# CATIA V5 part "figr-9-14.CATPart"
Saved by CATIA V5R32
Part number: Part2
Bounding box of the stored display mesh (mm): x -33.329 to 47.777, y -126.495 to 121.369, z -47.545 to 64.906
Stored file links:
  D:\PROJECTS\Project 2022\CATIA V5 6R 2022\Resources\Part Files\c09_catia_v5_6r2022_prt\c09_catia_v5_6r2022_prt\figr-9-14.CATPart
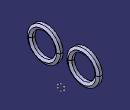
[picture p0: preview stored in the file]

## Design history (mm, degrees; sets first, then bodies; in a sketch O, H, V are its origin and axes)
Body1 (main body)
  Sketch1 on yz-plane, origin (0, 0, 0), H (0, 1, 0), V (0, 0, 1)
    circle A1 centre (-70.2613, 8.6726) radius 37.6716
    circle A2 centre (65.3061, 8.6726) radius 37.5
    radius A2 = 37.5
    radius A1 = 37.6716
  Plane1: type Angle, RefPlane yz-plane, Direction Sketch1.V, Angle 10
  Plane2: type Offset, RefPlane Plane1, Offset 55
  Sketch2 on Plane2, origin (44.5537, 64.0556, 0), H (-0.1736, 0.9848, 0), V (0, 0, 1)
    point P1 (-10.3597, -23.8575)
    point P2 (-2.157, -28.5933)
    point P3 (-2.157, -19.1216)
    point P4 (-10.3597, -14.3858)
    point P5 (-18.5625, -19.1216)
    point P6 (-18.5625, -28.5933)
    point P7 (-10.3597, -33.3292)
    point P8 (-2.157, -23.8575)
    line L1 (-2.157, -28.5933) -> (-2.157, -19.1216)
    line L2 (-2.157, -19.1216) -> (-10.3597, -14.3858)
    line L3 (-10.3597, -14.3858) -> (-18.5625, -19.1216)
    line L4 (-18.5625, -19.1216) -> (-18.5625, -28.5933)
    line L5 (-18.5625, -28.5933) -> (-10.3597, -33.3292)
    line L6 (-10.3597, -33.3292) -> (-2.157, -28.5933)
    construction line L7 (-10.3597, -23.8575) -> (-2.157, -23.8575)
    construction circle A1 centre (-10.3597, -23.8575) radius 9.4717
    construction arc A2 centre (-18.5625, -28.5933) radius 9.4717 from (-18.5625, -19.1216) to (-10.3597, -33.3292) cw
    construction arc A3 centre (-2.157, -19.1216) radius 9.4717 from (-10.3597, -14.3858) to (-2.157, -28.5933) ccw
    horizontal: L7 H
    coincidence: A1 P2, A1 P3, A1 P4, A1 P5, A1 P6, A1 P7, A2 P1, A3 P1
    midpoint: P8 L1
    parallelism: L1 L4
  Rib1: profile Sketch2, centre curve Sketch1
